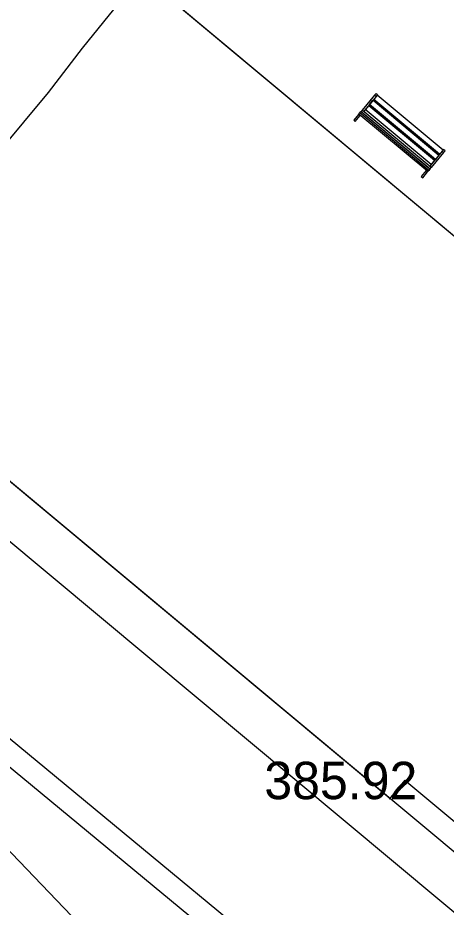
# Model space of a CAD drawing. Extents: x -438233 to -437334, y -1133133 to -1132623.
# Drawn here: x -438124.22 to -438115.63, y -1132995.04 to -1132977.21 of the extents above; entities that cross this region are included whole.
import ezdxf

# ---------------------------------------------------------------- set-up
doc = ezdxf.new("R2010")
doc.units = 0
for name, color, linetype in [('MOBILIÁŘ', 7, 'Continuous'), ('Vrstva 1', 7, 'Continuous'), ('Vrstva 10', 7, 'Continuous'), ('Vrstva 11', 7, 'Continuous'), ('Vrstva 3', 7, 'Continuous'), ('Vrstva 5', 7, 'Continuous'), ('Vrstva 52', 7, 'Continuous'), ('Vrstva 53', 7, 'Continuous')]:
    doc.layers.add(name, color=color, linetype=linetype)

# ---------------------------------------------------------------- blocks, each defined once
blk = doc.blocks.new('A$C6FF56919')
at = {"layer": 'Vrstva 1'}
for p, q in [((-18000, 5423), (-18000, 5482)), ((-18000, 5482), (-17605, 5482)), ((-18000, 5423), (0, 5423)), ((-18000, 5108), (-18000, 5423)), ((-17605, 5482), (-17605, 7031)), ((-17605, 5423), (-17605, 5482)), ((-401, 7031), (-401, 5482)), ((0, 7031), (-401, 7031)), ((-401, 5482), (0, 5482)), ((-401, 5423), (-401, 5482)), ((0, 5482), (0, 7031)), ((0, 5423), (0, 5482)), ((0, 5423), (0, 5108)), ((-18000, 5108), (0, 5108)), ((-18000, 4771), (-18000, 5108)), ((-18000, 4771), (0, 4771)), ((-18000, 4707), (-18000, 4771)), ((0, 4707), (-18000, 4707)), ((-18000, 4707), (-18000, 4365)), ((-18000, 459), (-18000, 4365)), ((-18000, 4365), (0, 4365)), ((-17605, 459), (-17605, 4365)), ((-17605, 3703), (-17594, 3703)), ((-17594, 2805), (-17594, 3895)), ((-401, 3703), (-411, 3703)), ((-401, 459), (-401, 4365)), ((0, 5108), (0, 4771)), ((0, 4771), (0, 4707)), ((0, 4365), (0, 4707)), ((0, 459), (0, 4365)), ((-17605, 2907), (-17594, 2907)), ((-17605, 2901), (-17594, 2901)), ((-17605, 2410), (-17594, 2410)), ((-411, 2805), (-17594, 2805)), ((-17594, 2805), (-17594, 2762)), ((-17594, 2762), (-411, 2762)), ((-17594, 2575), (-411, 2575)), ((-17594, 1475), (-17594, 2575)), ((-9200, 2575), (-9200, 2762)), ((-8799, 2575), (-8799, 2762)), ((-401, 2907), (-411, 2907)), ((-401, 2901), (-411, 2901)), ((-411, 2762), (-411, 2805)), ((-411, 2575), (-411, 1475)), ((-401, 2410), (-411, 2410)), ((-18000, 459), (-18000, 0)), ((-17605, 459), (-18000, 459)), ((-18000, 0), (-17605, 0)), ((-17605, 1608), (-17594, 1608)), ((-17605, 1608), (-17594, 1608)), ((-17605, 1106), (-17594, 1106)), ((-17605, 1106), (-17594, 1106)), ((-17605, 0), (-17605, 459)), ((-17605, 305), (-17594, 305)), ((-17594, 1459), (-17594, 1475)), ((-17594, 1475), (-411, 1475)), ((-411, 1459), (-17594, 1459)), ((-17594, 1245), (-17594, 1256)), ((-17594, 1256), (-411, 1256)), ((-17594, 1245), (-17594, 144)), ((-411, 1245), (-17594, 1245)), ((-17594, 144), (-411, 144)), ((-9200, 1256), (-9200, 1459)), ((-8800, 1256), (-8800, 1459)), ((-401, 1608), (-411, 1608)), ((-401, 1608), (-411, 1608)), ((-411, 1475), (-411, 1459)), ((-411, 1256), (-411, 1245)), ((-411, 144), (-411, 1245)), ((-401, 1106), (-411, 1106)), ((-401, 1106), (-411, 1106)), ((-401, 305), (-411, 305)), ((-401, 459), (0, 459)), ((-401, 0), (-401, 459)), ((0, 0), (-401, 0)), ((0, 459), (0, 0))]:
    blk.add_line(p, q, dxfattribs=at)
for points in [[(-17605, 7031), (-18000, 7031), (-18000, 5482)], [(-17594, 3895), (-411, 3895), (-411, 2805)]]:
    blk.add_lwpolyline(points, dxfattribs=at)

msp = doc.modelspace()

# ---------------------------------------------------------------- linework, layer by layer
at = {"layer": 'Vrstva 1'}
msp.add_line((-438116.779, -1132992.87), (-438116.779, -1132992.87), dxfattribs=at)
at = {"layer": 'Vrstva 10'}
msp.add_lwpolyline([(-438136.916, -1132976.04), (-438130.815, -1132968.777), (-438110.909, -1132985.383), (-438109.206, -1132983.342), (-438101.698, -1132989.616), (-438102.771, -1132990.9), (-438091.189, -1133000.578), (-438097.908, -1133008.583)], close=True, dxfattribs=at)
at = {"layer": 'Vrstva 11'}
for points in [[(-438138.792, -1132977.357), (-438140.226, -1132979.081), (-438130.239, -1132987.383), (-438111.696, -1133002.719), (-438101.614, -1133013.302)], [(-438138.453, -1132977.639), (-438139.605, -1132979.024), (-438129.958, -1132987.044), (-438111.395, -1133002.396), (-438101.295, -1133012.998)], [(-438128.485, -1132984.283), (-438112.774, -1132997.389), (-438110.127, -1132999.558), (-438098.962, -1133008.857)]]:
    msp.add_lwpolyline(points, dxfattribs=at)
at = {"layer": 'Vrstva 5'}
for p, q in [((-438130.84, -1132968.756), (-438110.909, -1132985.383)), ((-438136.916, -1132976.04), (-438116.764, -1132992.852)), ((-438116.463, -1132992.491), (-438116.779, -1132992.87)), ((-438116.463, -1132992.491), (-438111.878, -1132996.316))]:
    msp.add_line(p, q, dxfattribs=at)
at = {"layer": 'Vrstva 52'}
msp.add_lwpolyline([(-438128.855, -1132990.779), (-438128.856, -1132990.91), (-438128.989, -1132990.91), (-438128.989, -1132990.659), (-438128.93, -1132990.596), (-438129.59, -1132987.39), (-438128.59, -1132984.69), (-438123.607, -1132978.703), (-438122.927, -1132977.811), (-438122.184, -1132976.902), (-438122.789, -1132976.078), (-438121.848, -1132973.845), (-438121.368, -1132972.611), (-438119.619, -1132967.617), (-438116.421, -1132963.158), (-438109.667, -1132956.824), (-438099.67, -1132947.487), (-438095.701, -1132943.378), (-438089.916, -1132937.924), (-438083.958, -1132932.455), (-438080.074, -1132928.641), (-438079.488, -1132927.786), (-438078.793, -1132926.015), (-438077.623, -1132919.546)], dxfattribs=at)
at = {"layer": 'Vrstva 53'}
msp.add_lwpolyline([(-438111.68, -1133002.95), (-438112.12, -1133002.5), (-438122.55, -1132995.83), (-438124.94, -1132993.34), (-438127.48, -1132990.73), (-438128.12, -1132989.43), (-438134.1, -1132984.54), (-438140.26, -1132979.82), (-438141.19, -1132978.73), (-438141.97, -1132973.72), (-438142.51, -1132968.08), (-438140.08, -1132963.83), (-438137.6, -1132962.74), (-438135.49, -1132962.32), (-438133.71, -1132961.01), (-438132.67, -1132959.55), (-438131.52, -1132960.06), (-438130.71, -1132960.47)], dxfattribs=at)

# ---------------------------------------------------------------- block references
at = {"layer": 'MOBILIÁŘ', "xscale": 0.0001, "yscale": 0.00010000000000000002, "rotation": 140.22668670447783}
msp.add_blockref('A$C6FF56919', (-438117.038, -1132978.72), dxfattribs=at)

# ---------------------------------------------------------------- texts
at = {"layer": 'Vrstva 3'}
msp.add_text('385.92 ', height=0.75, dxfattribs=at).set_placement((-438119.279, -1132992.87))

doc.saveas('drawing.dxf')
